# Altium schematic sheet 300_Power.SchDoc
size A; SheetNumber: 5; SheetTotal: 5
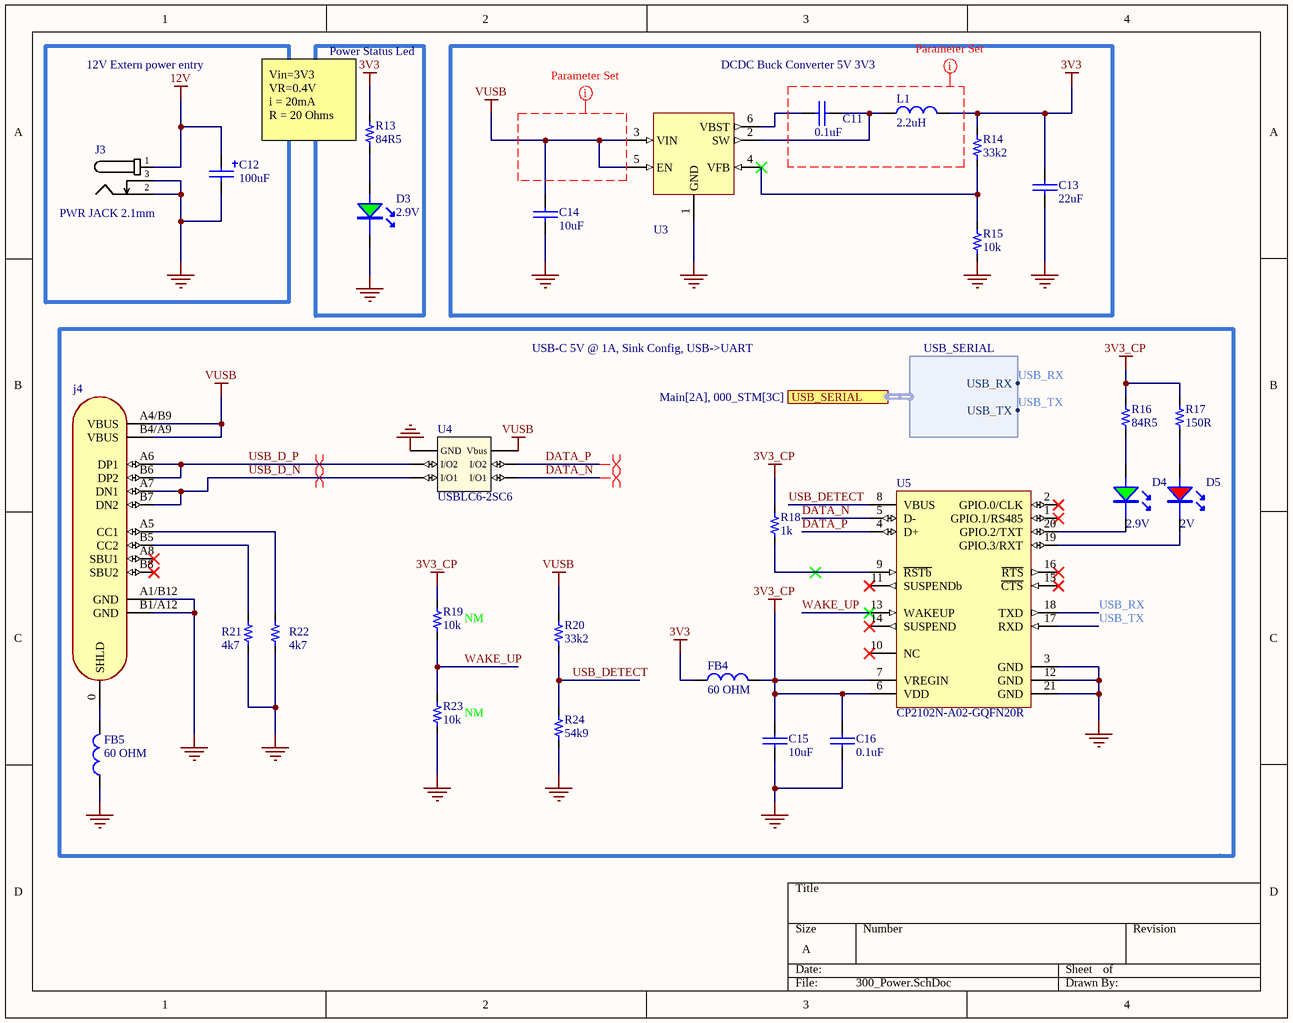
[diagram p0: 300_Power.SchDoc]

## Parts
C11  value 0.1uF  [0603_cap]  (hidden comment: 0.1uF 50V)
C12  value 100uF  [CAP_TH_2.5MM_6.3*12MM]  (hidden comment: 100uF 35V)
C13  value 22uF  [0603_cap]  (hidden comment: 22uF 10V)
C14  value 10uF  [0603_cap]  (hidden comment: 10uF 10V)
C15  value 10uF  [0603_cap]  (hidden comment: 10uF 10V)
C16  value 0.1uF  [0603_cap]  (hidden comment: 0.1uF 50V)
D3  2.9V  [0805_LED]
D4  2.9V  [0805_LED]
D5  2V  [0805_LED]
FB4  value 60 OHM  [0603_fb]  (hidden comment: 60OHM 2A)
FB5  value 60 OHM  [0603_fb]  (hidden comment: 60OHM 2A)
J3  PWR JACK 2.1mm  [CON_POWER_BARREL_2.1MM_3CONN]
j4  USB C  [CON_USB_C_16P_RA]  (value not drawn)
L1  value 2.2uH  [Ind_5.8*5.2_NS]  (hidden comment: 2.2uH 4A)
R13  value 84R5  [0603_res]  (hidden comment: 84R5 1/10W)
R14  value 33k2  [0603_res]  (hidden comment: 33k2 1/10W)
R15  value 10k  [0603_res]  (hidden comment: 10k 1/10W)
R16  value 84R5  [0603_res]  (hidden comment: 84R5 1/10W)
R17  value 150R  [0603_res]  (hidden comment: 150R 1/10W)
R18  value 1k  [0603_res]  (hidden comment: 1k 1/10W)
R19  value 10k  Usage: NM  [0603_res]  (hidden comment: 10k 1/10W)
R20  value 33k2  [0603_res]  (hidden comment: 33k2 1/10W)
R21  value 4k7  [0603_res]  (hidden comment: 4k7 1/10W)
R22  value 4k7  [0603_res]  (hidden comment: 4k7 1/10W)
R23  value 10k  Usage: NM  [0603_res]  (hidden comment: 10k 1/10W)
R24  value 54k9  [0603_res]  (hidden comment: 54k9 1/10W)
U3  TPS564201DDCR  [SOT_23_6]  (value not drawn)
U4  USBLC6-2SC6  [SOT_23_6]
U5  CP2102N-A02-GQFN20R  [WFQFN_20_EP_3X3MM]

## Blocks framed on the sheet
12V Extern power entry: C12 J3
Power Status Led: D3 R13
DCDC Buck Converter 5V 3V3: C11 C13 C14 L1 R14 R15 U3
USB-C 5V @ 1A, Sink Config, USB->UART: C15 C16 D4 D5 FB4 FB5 j4 R16-R24 U4 U5

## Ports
USB_SERIAL (harness USB_SERIAL, see Main[2A], 000_STM[3C])

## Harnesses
USB_SERIAL: USB_RX, USB_TX

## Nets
3V3: C13.1 FB4.1 L1.2 R13.1 R14.2
3V3_CP: C15.1 C16.1 FB4.2 R16.2 R17.2 R18.2 R19.2 U5.6(VDD) U5.7(VREGIN)
12V: C12.1 J3.1
GND: C12.2 C13.2 C14.2 C15.2 C16.2 D3.2 FB5.1 J3.2 J3.3 j4.A1/B12(GND) j4.B1/A12(GND) R15.1 R21.1 R22.1 R23.1 R24.1 U3.1(GND) U4.2(GND) U5.3(GND) U5.12(GND) U5.21(GND)
VUSB: C14.1 j4.A4/B9(VBUS) j4.B4/A9(VBUS) R20.2 U3.3(VIN) U3.5(EN) U4.5(Vbus)
DATA_N: U4.6(I/O1) U5.5(D-)
DATA_P: U4.4(I/O2) U5.4(D+)
USB_D_N: j4.A7(DN1) j4.B7(DN2) U4.1(I/O1)
USB_D_P: j4.A6(DP1) j4.B6(DP2) U4.3(I/O2)
USB_DETECT: R20.1 R24.2 U5.8(VBUS)
USB_RX: U5.18(TXD) ; port USB_SERIAL.USB_RX
USB_TX: U5.17(RXD) ; port USB_SERIAL.USB_TX
WAKE_UP: R19.1 R23.2 U5.13(WAKEUP)
NetC11_1: C11.1 L1.1 U3.2(SW)
NetC11_2: C11.2 U3.6(VBST)
NetD3_1: D3.1(A) R13.2
NetD4_1: D4.1(A) R16.1
NetD4_2: D4.2 U5.20(GPIO.2/TXT)
NetD5_1: D5.1(A) R17.1
NetD5_2: D5.2 U5.19(GPIO.3/RXT)
NetFB5_2: FB5.2 j4.0(SHLD)
Netj4_A5: j4.A5(CC1) R22.2
Netj4_B5: j4.B5(CC2) R21.2
NetR14_1: R14.1 R15.2 U3.4(VFB)
NetR18_1: R18.1 U5.9(~{RSTb})

Not connected (* = marked no-connect by the designer): j4 A8(SBU1)* B8(SBU2)*; U5 1(GPIO.1/RS485)* 2(GPIO.0/CLK)* 10(NC)* 11(SUSPENDb)* 14(SUSPEND)* 15(~{CTS})* 16(~{RTS})*

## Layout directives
differential pair; differential pair class USB_2.0_MCU: DATA_N, DATA_P, USB_D_N, USB_D_P
net class 5V_1A: (no net found under the mark)

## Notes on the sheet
- (near R13) Vin=3V3
  VR=0.4V
  i = 20mA
  R = 20 Ohms

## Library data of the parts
C11 C16 = Cap_0.1uF_0603_50V: 50V 100nF Y5V -20%~+80% 0603 Multilayer Ceramic Capacitors MLCC - SMD/SMT ROHS; Manufacturer: Walsin Tech Corp; Manufacturer Part Number: 0603F104Z500CT
C12 = Cap_100uF_ALU_TH_35V: 100uF 35V ±20% Plugin,D6.3xL12mm Aluminum Electrolytic Capacitors - Leaded ROHS; Manufacturer: HRK; Manufacturer Part Number: 35V100uF CD110
C13 = Cap_22uF_0603_10V: 10V 22uF X5R ±20% 0603 Multilayer Ceramic Capacitors MLCC - SMD/SMT ROHS; Manufacturer: HRE; Manufacturer Part Number: CGA0603X5R226M100JT
C14 C15 = Cap_10uF_0603_10V: 10V 10uF X5R ±10% 0603 Multilayer Ceramic Capacitors MLCC - SMD/SMT ROHS; Manufacturer: CCTC; Manufacturer Part Number: TCC0603X5R106K100CT
D3 D4 = LED_0805_Green: LED GREEN CLEAR 0805 SMD; Manufacturer: XINGLIGHT; Manufacturer Part Number: XL-2012UGC
D5 = LED_0805_RED: LED RED CLEAR 0805 SMD; Manufacturer: XINGLIGHT; Manufacturer Part Number: XL-2012SURC
FB4 FB5 = FB_60_0603_2A: 2A 1 100mΩ 60Ω@100MHz ±25% 0603 Ferrite Beads ROHS; Manufacturer: TAI-TECH; Manufacturer Part Number: HCB1608KF-600T20
J3 = Con_Power_Jack_2.1mm_3pins: CONN PWR JACK 2X5.5MM SOLDER; Manufacturer: HCTL; Manufacturer Part Number: HC-DC-005-2.0T
j4 = CON_USB_TYPEC_16P: 3A USB 3.1 1 Surface Mount 16P Female -40℃~+85℃ Type-C SMD USB Connectors ROHS; Manufacturer: SHOU HAN; Manufacturer Part Number: TYPE-C-3.1-16PIN
L1 = Inductor_2.2uH_4A_5.8*5.2mm: 4A 2.2uH ±20% 22.1mΩ SMD,5.8x5.2mm Inductors (SMD) ROHS; Manufacturer: SHOU HAN; Manufacturer Part Number: CY54-2.2UH
R13 R16 = Res_84R5_0603_1/10W: 100mW Thick Film Resistor 50V ±100ppm/℃ ±1% 84.5Ω 0603 Chip Resistor - Surface Mount ROHS; Manufacturer: LIZ Elec; Manufacturer Part Number: CR0603FA84R5G
R14 R20 = Res_33k2_0603_1/10W: 100mW Thick Film Resistor 75V ±100ppm/℃ ±1% 33.2kΩ 0603 Chip Resistor - Surface Mount ROHS; Manufacturer: YAGEO; Manufacturer Part Number: RC0603FR-0733K2L
R15 R19 R23 = Res_10k_0603_1/10W: RES SMD 10k OHM 5% 1/10W 0603; Manufacturer: FOJAN; Manufacturer Part Number: FRC0603J103TS
R17 = Res_150R_0603_1/10W: 100mW Thick Film Resistor 75V ±100ppm/℃ ±1% 150Ω 0603 Chip Resistor - Surface Mount ROHS; Manufacturer: RALEC; Manufacturer Part Number: RTT031500FTP
R18 = Res_1k_0603_1/10W: RES SMD 1k OHM 5% 1/10W 0603; Manufacturer: FOJAN; Manufacturer Part Number: FRC0603J102 TS
R21 R22 = Res_4k7_0603_1/10W: 100mW Thick Film Resistor 75V ±1% 4.7kΩ 0603 Chip Resistor - Surface Mount ROHS; Manufacturer: VO; Manufacturer Part Number: SCR0603F4K7
R24 = Res_54k9_0603_1/10W: 100mW Thick Film Resistor 75V ±100ppm/℃ ±1% 54.9kΩ 0603 Chip Resistor - Surface Mount ROHS; Manufacturer: YAGEO; Manufacturer Part Number: RC0603FR-0754K9L
U3 = DCDC_SW_BUCK_4A_SOT23-6: IC REG BUCK ADJ 4A SOT23; Manufacturer: Texas Instruments
U4 = TVS_5.25V_2CH_SOT_23_6: TVS DIODE 5.25V 17V SOT23-6; Manufacturer: STMicroelectronics
U5 = IC_SGL_USB2UART-BRIDGE_20QFN: IC USB TO UART BRIDGE QFN20; Manufacturer: Silicon Labs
